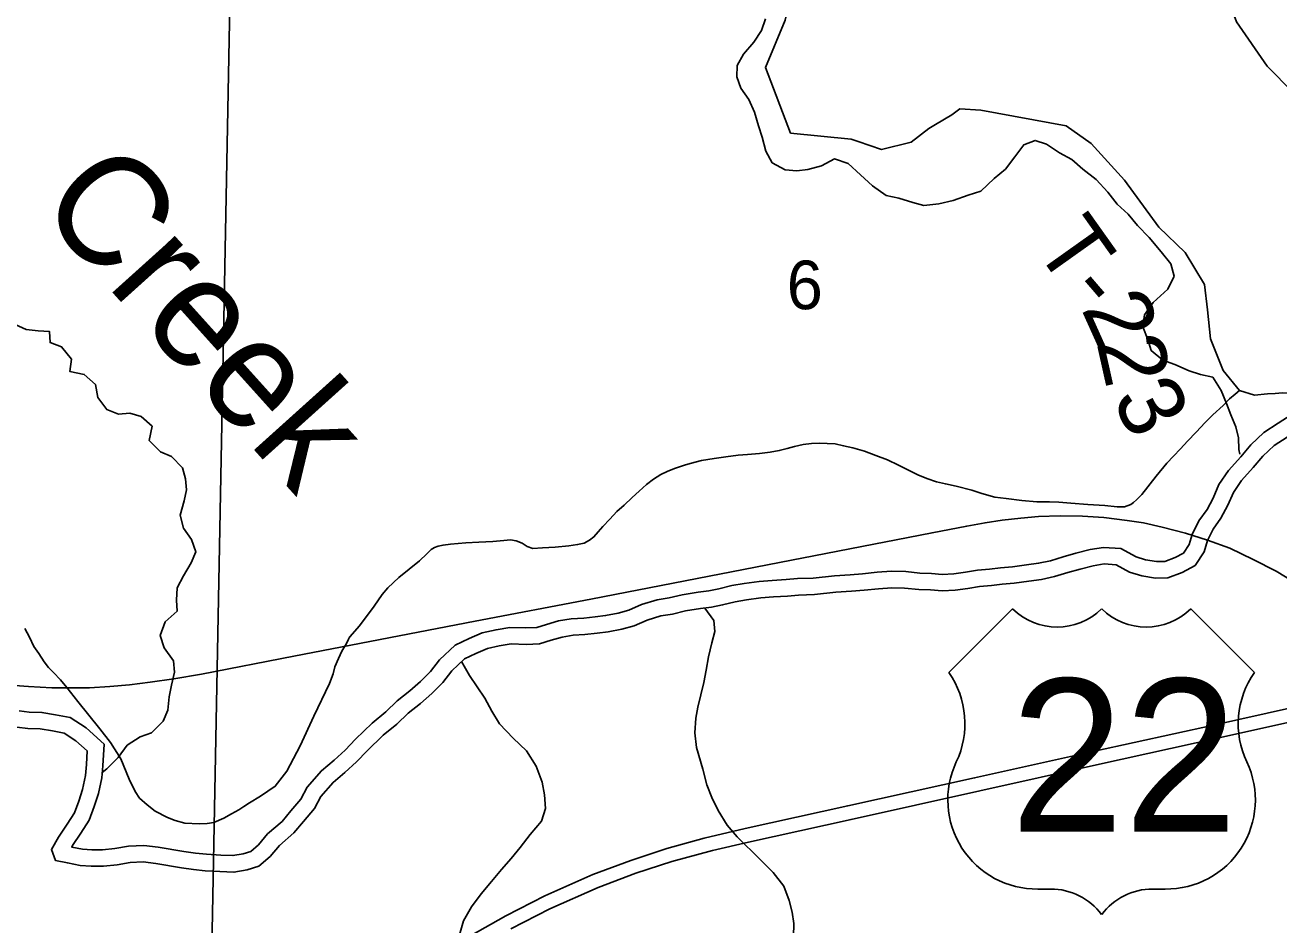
# Model space of a CAD drawing. Extents: x -19 to 40.8, y -1.8 to 26.1.
# Drawn here: x 3.175 to 4.257, y 14.667 to 15.443 of the extents above; entities that cross this region are included whole.
import ezdxf

# ---------------------------------------------------------------- set-up
doc = ezdxf.new("R2010")
doc.units = 0
for name, color, linetype in [('GM_X_Interchange_Ramps', 7, 'Continuous'), ('GM_X_Minor_River', 7, 'Continuous'), ('GM_X_Section', 7, 'Continuous'), ('GM_X_Section_Text', 7, 'Continuous'), ('GM_X_State_Route', 7, 'Continuous'), ('GM_X_State_Shield', 7, 'Continuous'), ('GM_X_Township_Road', 7, 'Continuous'), ('GM_X_Township_Road_Text', 7, 'Continuous'), ('GM_X_Unincorporated_Location', 7, 'Continuous'), ('RW_P_Text', 7, 'Continuous')]:
    doc.layers.add(name, color=color, linetype=linetype)

msp = doc.modelspace()

# ---------------------------------------------------------------- linework, layer by layer
at = {"layer": 'GM_X_Interchange_Ramps'}
msp.add_lwpolyline([(4.2703, 14.9621), (4.2543, 14.9719), (4.2343, 14.9821), (4.2142, 14.9918), (4.1949, 14.9988), (4.176, 15.0048), (4.156, 15.0099), (4.1397, 15.0135), (4.1257, 15.0157), (4.1054, 15.0183), (4.0871, 15.0194), (4.0678, 15.0197), (4.0492, 15.019), (4.034, 15.0177), (4.0177, 15.016), (4.003, 15.0137), (3.9873, 15.0109), (3.9573, 15.0051), (3.663, 14.9479), (3.5632, 14.9288), (3.4066, 14.8986), (3.327, 14.8831), (3.303, 14.8791), (3.2825, 14.8761), (3.2649, 14.8739), (3.2478, 14.8723), (3.2303, 14.8714), (3.2144, 14.8713), (3.1979, 14.8714), (3.1777, 14.8723), (3.1582, 14.8739)], dxfattribs=at)
at = {"layer": 'GM_X_Section'}
for points in [[(3.8136, 15.4486), (3.8102, 15.4383), (3.8035, 15.4283), (3.7945, 15.418), (3.7892, 15.4081), (3.7889, 15.3986), (3.7924, 15.3887), (3.7993, 15.3789), (3.804, 15.3679), (3.8075, 15.3562), (3.8106, 15.3463), (3.8138, 15.3342), (3.8192, 15.3243), (3.8306, 15.3183), (3.8405, 15.3173), (3.85, 15.3185), (3.8618, 15.3216), (3.8731, 15.3278), (3.8849, 15.3237), (3.8956, 15.3139), (3.906, 15.3045), (3.9178, 15.2962), (3.9285, 15.2937), (3.9407, 15.29), (3.9502, 15.2874), (3.9631, 15.289), (3.9756, 15.2918), (3.9885, 15.2964), (3.9995, 15.2999), (4.0108, 15.3107), (4.0206, 15.3187), (4.0288, 15.3294), (4.0364, 15.3398), (4.0462, 15.3436), (4.0561, 15.3403), (4.0672, 15.3328), (4.0779, 15.3272), (4.0874, 15.3189), (4.0989, 15.3099), (4.1089, 15.2989), (4.117, 15.2887), (4.1265, 15.2801), (4.1346, 15.2702), (4.1446, 15.2597), (4.1549, 15.2476), (4.1634, 15.237), (4.1661, 15.2264), (4.1609, 15.2153), (4.1481, 15.2038), (4.1406, 15.1931), (4.1391, 15.1829), (4.1434, 15.1719), (4.1465, 15.1624), (4.1565, 15.1541), (4.1668, 15.1504), (4.1793, 15.1448), (4.1889, 15.1415), (4.1995, 15.1393), (4.2068, 15.1279), (4.2115, 15.1166), (4.215, 15.1067), (4.2193, 15.0965), (4.2216, 15.087), (4.2221, 15.0768), (4.2229, 15.073)], [(3.1662, 15.1849), (3.1757, 15.1805), (3.186, 15.1794), (3.1959, 15.1787), (3.1963, 15.1692), (3.2062, 15.1655), (3.2147, 15.1549), (3.2133, 15.1443), (3.2258, 15.1417), (3.2354, 15.1331), (3.2374, 15.1217), (3.2451, 15.1115), (3.2554, 15.1074), (3.2652, 15.1082), (3.2748, 15.1053), (3.2843, 15.097), (3.2818, 15.0848), (3.2914, 15.075), (3.3009, 15.0709), (3.3105, 15.0611), (3.3132, 15.0516), (3.314, 15.0421), (3.3119, 15.0326), (3.3085, 15.0204), (3.3113, 15.009), (3.3182, 14.9992), (3.3221, 14.9886), (3.318, 14.9791), (3.3113, 14.968), (3.306, 14.9577), (3.3054, 14.947), (3.3058, 14.9375), (3.2956, 14.9283), (3.2912, 14.9165), (3.2947, 14.9059)], [(4.2713, 15.1093), (4.2561, 15.0997), (4.2437, 15.0917), (4.2323, 15.081), (4.2237, 15.0706), (4.213, 15.0589), (4.2049, 15.0466), (4.1999, 15.035), (4.1946, 15.0252), (4.1876, 15.0154), (4.1818, 15.0035), (4.1791, 14.9949), (4.1743, 14.9876), (4.1672, 14.9836), (4.1581, 14.9802), (4.1511, 14.9802), (4.1415, 14.9817), (4.1333, 14.9842), (4.1203, 14.9914), (4.1052, 14.9924), (4.0936, 14.9905), (4.0814, 14.9875), (4.0704, 14.9843), (4.0595, 14.9809), (4.0492, 14.9788), (4.0388, 14.9773), (4.0267, 14.9757), (4.0165, 14.9749), (4.007, 14.9736), (3.9965, 14.9728), (3.9862, 14.9711), (3.976, 14.9696), (3.9661, 14.9692), (3.9568, 14.9699), (3.9468, 14.9702), (3.9346, 14.9716), (3.9223, 14.9719), (3.91, 14.971), (3.8973, 14.9697)], [(3.8987, 14.9556), (3.9112, 14.9568), (3.9226, 14.9577), (3.9336, 14.9574), (3.9458, 14.956), (3.9561, 14.9557), (3.9659, 14.955), (3.9773, 14.9555), (3.9883, 14.9571), (3.9982, 14.9587), (4.0085, 14.9595), (4.0179, 14.9607), (4.0282, 14.9616), (4.0407, 14.9632), (4.0517, 14.9648), (4.0631, 14.9672), (4.0745, 14.9707), (4.0851, 14.9738), (4.0964, 14.9766), (4.1059, 14.9782), (4.1162, 14.9775), (4.1276, 14.9711), (4.1383, 14.9678), (4.1501, 14.966), (4.1607, 14.9661), (4.1732, 14.9707), (4.1842, 14.9769), (4.1921, 14.9887), (4.195, 14.9983), (4.1999, 15.0082), (4.2066, 15.0177), (4.2126, 15.0288), (4.2175, 15.0399), (4.2242, 15.0502), (4.2344, 15.0613), (4.2427, 15.0712), (4.2525, 15.0804), (4.2638, 15.0877)], [(3.8973, 14.9697), (3.8867, 14.9689), (3.8732, 14.968), (3.8548, 14.966), (3.8412, 14.9655), (3.8315, 14.9647), (3.8194, 14.9638), (3.808, 14.9629), (3.7953, 14.9612), (3.7846, 14.9595), (3.7733, 14.9567), (3.7646, 14.9549), (3.7555, 14.9537), (3.7418, 14.9516), (3.7304, 14.9488), (3.7202, 14.9472), (3.7067, 14.9431), (3.6956, 14.9382), (3.6865, 14.9358), (3.6756, 14.9336), (3.6667, 14.9325), (3.6567, 14.9313), (3.646, 14.9309), (3.6349, 14.929), (3.6245, 14.926), (3.6162, 14.9234), (3.6068, 14.923), (3.5931, 14.9233), (3.5811, 14.9214), (3.5691, 14.9187), (3.5579, 14.9138), (3.5458, 14.9081), (3.5324, 14.8955), (3.5244, 14.8853), (3.5159, 14.8767), (3.5068, 14.8688), (3.4958, 14.8601), (3.486, 14.8505), (3.4743, 14.8409), (3.4597, 14.8269), (3.4509, 14.8175), (3.4413, 14.8088), (3.4304, 14.7998), (3.4181, 14.7855), (3.4125, 14.7752), (3.404, 14.7651), (3.3964, 14.756), (3.384, 14.7453), (3.3761, 14.7357), (3.3695, 14.73), (3.3629, 14.728), (3.354, 14.7265), (3.3435, 14.727), (3.3313, 14.7277), (3.3216, 14.7287), (3.3118, 14.7301), (3.2896, 14.7337), (3.2771, 14.7353), (3.264, 14.7348), (3.2522, 14.7327), (3.2416, 14.7316), (3.2322, 14.7315), (3.2241, 14.7321), (3.2149, 14.7339), (3.2155, 14.7351), (3.2228, 14.7458), (3.23, 14.7571), (3.2344, 14.7688), (3.2381, 14.78), (3.241, 14.7935), (3.2417, 14.8041), (3.2428, 14.8228), (3.2274, 14.8368), (3.2137, 14.8457), (3.2009, 14.8481), (3.1892, 14.8501), (3.1781, 14.8504), (3.1695, 14.8513)], [(3.1676, 14.8372), (3.1771, 14.8362), (3.1878, 14.8359), (3.1984, 14.8341), (3.2083, 14.8323), (3.2186, 14.8255), (3.2282, 14.8168), (3.2276, 14.805), (3.2269, 14.7955), (3.2243, 14.7837), (3.221, 14.7735), (3.2173, 14.7635), (3.2109, 14.7536), (3.2034, 14.7425), (3.1974, 14.7318), (3.2009, 14.7224), (3.2112, 14.7202), (3.2222, 14.718), (3.2317, 14.7173), (3.2424, 14.7174), (3.2541, 14.7186), (3.2655, 14.7206), (3.2765, 14.7211), (3.2876, 14.7196), (3.3096, 14.716), (3.3199, 14.7146), (3.3302, 14.7135), (3.3427, 14.7129), (3.3549, 14.7122), (3.3662, 14.7142), (3.3765, 14.7173), (3.3863, 14.7258), (3.3942, 14.7353), (3.4066, 14.7461), (3.4149, 14.756), (3.4243, 14.7671), (3.4299, 14.7774), (3.4404, 14.7897), (3.4506, 14.7981), (3.4608, 14.8073), (3.4698, 14.8169), (3.4838, 14.8303), (3.4955, 14.8399), (3.5053, 14.8495), (3.5158, 14.8579), (3.5256, 14.8663), (3.5351, 14.8759), (3.5429, 14.8859), (3.5539, 14.8962), (3.5637, 14.9008), (3.5736, 14.9051), (3.5838, 14.9075), (3.594, 14.9091), (3.607, 14.9088), (3.6187, 14.9093), (3.6286, 14.9124), (3.6381, 14.9151), (3.6475, 14.9167), (3.6578, 14.9172), (3.6684, 14.9184), (3.6779, 14.9196), (3.6897, 14.922), (3.7003, 14.9247), (3.7116, 14.9298), (3.7234, 14.9333), (3.7332, 14.9349), (3.7446, 14.9376), (3.7575, 14.9396), (3.767, 14.9409), (3.7765, 14.9428), (3.7875, 14.9456), (3.7973, 14.9472), (3.8095, 14.9488), (3.8205, 14.9497), (3.8326, 14.9505), (3.8421, 14.9513), (3.8558, 14.9518), (3.8744, 14.9539), (3.8877, 14.9548), (3.8987, 14.9556)], [(3.7612, 14.9401), (3.769, 14.9295), (3.7698, 14.92), (3.7673, 14.9101), (3.7643, 14.8979), (3.7625, 14.8865), (3.7603, 14.8758), (3.7552, 14.8545), (3.7534, 14.845), (3.7527, 14.8324), (3.754, 14.8199), (3.7595, 14.801), (3.763, 14.7877), (3.7673, 14.7767), (3.7727, 14.7653), (3.7804, 14.7529), (3.7892, 14.7427), (3.8091, 14.7231), (3.8202, 14.7118), (3.8295, 14.7001), (3.8341, 14.6879), (3.8365, 14.6777), (3.8381, 14.6678), (3.8378, 14.6568)], [(3.2947, 14.9059), (3.3028, 14.8946), (3.3036, 14.8847), (3.3011, 14.8737), (3.2989, 14.8634), (3.2978, 14.852), (3.2937, 14.8424), (3.2839, 14.8325), (3.2741, 14.829), (3.2627, 14.8217), (3.2549, 14.8113), (3.2451, 14.8014), (3.2413, 14.7983)], [(3.5514, 14.8939), (3.5582, 14.8818), (3.5713, 14.8625), (3.5774, 14.8512), (3.584, 14.8402), (3.5959, 14.8278), (3.6074, 14.8168), (3.6158, 14.8036), (3.6209, 14.79), (3.6229, 14.779), (3.6237, 14.7672), (3.6204, 14.7561), (3.6106, 14.7447), (3.602, 14.7336), (3.5941, 14.724), (3.5858, 14.7144), (3.5772, 14.7041), (3.5681, 14.6934), (3.5599, 14.6823), (3.5531, 14.6701), (3.5495, 14.6583)]]:
    msp.add_lwpolyline(points, dxfattribs=at)
at = {"layer": 'GM_X_State_Route'}
for points in [[(4.3257, 15.3498), (4.3251, 15.3505), (4.2689, 15.3849), (4.2466, 15.4076), (4.2199, 15.4459), (4.2025, 15.4933), (4.1605, 15.58), (4.1444, 15.6081), (4.1337, 15.6283), (4.1173, 15.6538), (4.0927, 15.6836), (4.0704, 15.7184), (4.0341, 15.8035), (4.0106, 15.82), (3.993, 15.8334), (3.9881, 15.843), (3.9886, 15.8546), (3.9895, 15.8715), (3.9882, 15.8783)], [(3.8936, 15.3428), (3.8875, 15.3448), (3.8353, 15.35), (3.8135, 15.4066), (3.8306, 15.4474), (3.843, 15.5014), (3.8436, 15.5139)], [(4.2225, 15.1277), (4.2084, 15.1452), (4.1975, 15.1723), (4.195, 15.1975), (4.1924, 15.2192), (4.1758, 15.2468), (4.1531, 15.2688), (4.1233, 15.3094), (4.0946, 15.341), (4.0729, 15.3561), (3.9994, 15.3697), (3.9814, 15.3708), (3.9745, 15.3656), (3.9603, 15.3572)], [(3.9603, 15.3572), (3.9546, 15.3539), (3.9392, 15.3421), (3.9138, 15.3358), (3.8936, 15.3428)], [(4.2225, 15.1277), (4.2189, 15.1246), (4.214, 15.1207), (4.2085, 15.115), (4.1997, 15.1068), (4.1929, 15.1002), (4.1852, 15.0919), (4.1778, 15.084), (4.1716, 15.0774), (4.1657, 15.0712), (4.16, 15.065), (4.1507, 15.054), (4.1382, 15.038), (4.1336, 15.0336), (4.1312, 15.0312), (4.1287, 15.0294), (4.1233, 15.0275), (4.1169, 15.0275), (4.1065, 15.0285), (4.0918, 15.0296), (4.0771, 15.0307), (4.0668, 15.0316), (4.0586, 15.0318), (4.0476, 15.0318), (4.0349, 15.033), (4.0212, 15.0345), (4.0114, 15.0358), (4.0003, 15.0389), (3.9915, 15.0417), (3.9781, 15.0453), (3.9689, 15.0472), (3.9612, 15.049), (3.9527, 15.0518), (3.945, 15.0551), (3.9375, 15.0587), (3.9283, 15.0635), (3.9188, 15.0679), (3.9087, 15.0717), (3.899, 15.0754), (3.8889, 15.0784), (3.881, 15.0802), (3.8737, 15.0818), (3.8667, 15.082), (3.8603, 15.0824), (3.8533, 15.082), (3.846, 15.0811), (3.8386, 15.0796), (3.8322, 15.0778), (3.8254, 15.076), (3.8176, 15.0745), (3.8084, 15.0736), (3.7981, 15.0725), (3.7899, 15.0719), (3.7794, 15.0705), (3.7693, 15.0692), (3.7583, 15.0673), (3.7486, 15.0648), (3.7438, 15.0633), (3.7352, 15.0606), (3.7286, 15.058), (3.7233, 15.0554), (3.717, 15.0512), (3.711, 15.0466), (3.7046, 15.0409), (3.6985, 15.0354), (3.6915, 15.029), (3.6853, 15.0235), (3.6792, 15.0169), (3.6732, 15.0105), (3.6693, 15.0059), (3.6655, 15.0015), (3.6618, 14.9986), (3.6572, 14.9962), (3.6514, 14.9949), (3.644, 14.9938), (3.6321, 14.9927), (3.6213, 14.992), (3.6128, 14.9916), (3.6079, 14.9932), (3.6037, 14.996), (3.5983, 14.998), (3.5935, 14.9989), (3.5877, 14.9984), (3.5784, 14.9976), (3.5662, 14.9969), (3.5551, 14.9965), (3.5418, 14.9953), (3.5354, 14.9945), (3.531, 14.9934), (3.5279, 14.9923), (3.525, 14.9905), (3.5215, 14.9868), (3.5151, 14.9809), (3.4971, 14.9665), (3.4877, 14.9577), (3.4827, 14.9518), (3.476, 14.9417), (3.4632, 14.9247), (3.455, 14.9154), (3.4544, 14.9144)], [(4.343, 15.1054), (4.3357, 15.1139), (4.3291, 15.1194), (4.3195, 15.127), (4.316, 15.129), (4.3128, 15.1303), (4.309, 15.1312), (4.3046, 15.1308), (4.2964, 15.1287), (4.2914, 15.1264), (4.2863, 15.1246), (4.2796, 15.1242), (4.2697, 15.1251), (4.2596, 15.1257), (4.2534, 15.1253), (4.2468, 15.1249), (4.2355, 15.1239), (4.2225, 15.1277)], [(3.4544, 14.9144), (3.4539, 14.9134), (3.452, 14.9096), (3.4479, 14.903), (3.445, 14.8967), (3.4421, 14.8894), (3.4406, 14.8834), (3.4374, 14.8749), (3.4238, 14.8469), (3.4122, 14.8213), (3.4005, 14.7994), (3.3905, 14.7864), (3.3779, 14.7777), (3.3683, 14.772), (3.3634, 14.7689), (3.359, 14.7661), (3.3527, 14.7625), (3.3463, 14.7588), (3.3375, 14.755), (3.3318, 14.7542), (3.325, 14.7539), (3.3126, 14.7545), (3.3041, 14.7567), (3.2975, 14.7595), (3.287, 14.7649), (3.2799, 14.7704), (3.2735, 14.7761), (3.2696, 14.7819), (3.2645, 14.7926), (3.2572, 14.8101), (3.2484, 14.8241), (3.2393, 14.836), (3.2201, 14.8595), (3.2107, 14.8716), (3.2052, 14.8782), (3.1992, 14.8845), (3.195, 14.8887), (3.1913, 14.8936), (3.1865, 14.9008), (3.1823, 14.907), (3.1785, 14.9149), (3.1744, 14.9224)]]:
    msp.add_lwpolyline(points, dxfattribs=at)
at = {"layer": 'GM_X_State_Shield'}
for p, q in [((4.0267, 14.9394), (3.9718, 14.8845)), ((4.2354, 14.8845), (4.1805, 14.9394)), ((4.0487, 14.6977), (4.0597, 14.6977)), ((4.1476, 14.6977), (4.1585, 14.6977))]:
    msp.add_line(p, q, dxfattribs=at)
for centre, radius, start, end in [((4.0652, 14.9786), 0.0549, 225.573, 314.427), ((4.1421, 14.9786), 0.0549, 225.573, 314.427), ((3.9088, 14.8404), 0.0769, 334.5471, 35.0009), ((4.2984, 14.8404), 0.0769, 144.9991, 205.4529), ((4.0478, 14.7746), 0.0769, 154.8319, 270.6383), ((4.1594, 14.7746), 0.0769, 269.3617, 25.1681), ((4.0597, 14.6428), 0.0549, 36.8699, 90), ((4.1476, 14.6428), 0.0549, 90, 143.1301)]:
    msp.add_arc(centre, radius, start, end, dxfattribs=at)
at = {"layer": 'GM_X_Township_Road'}
for points in [[(3.5585, 14.6569), (3.5894, 14.6745), (3.6232, 14.6919), (3.6647, 14.7102), (3.6973, 14.7224), (3.7285, 14.7327), (3.7608, 14.7417), (3.7961, 14.7499), (3.8846, 14.7696), (3.994, 14.7936), (4.0975, 14.8166), (4.2003, 14.8392), (4.2682, 14.8544)], [(3.5938, 14.6633), (3.6276, 14.6807), (3.6691, 14.699), (3.7016, 14.7113), (3.7329, 14.7215), (3.7678, 14.7308), (3.7989, 14.738), (3.8874, 14.7577), (3.9984, 14.7824), (4.1019, 14.8054), (4.2047, 14.828), (4.271, 14.8427)]]:
    msp.add_lwpolyline(points, dxfattribs=at)
at = {"layer": 'RW_P_Text'}
for points in [[(2.3634, 15.8992), (3.3595, 15.883), (3.3355, 14.6314), (2.3446, 14.653)], [(3.3595, 15.883), (4.3635, 15.8676), (4.3391, 14.8802), (4.3324, 14.6079), (3.3355, 14.6314)]]:
    msp.add_lwpolyline(points, close=True, dxfattribs=at)

# ---------------------------------------------------------------- texts
at = {"layer": 'GM_X_Minor_River'}
msp.add_text('Creek', height=0.09469, rotation=311.9835, dxfattribs=at).set_placement((3.183, 15.2869))
at = {"layer": 'GM_X_Section_Text'}
msp.add_text('6', height=0.0419, rotation=0, dxfattribs=at).set_placement((3.8319, 15.198))
at = {"layer": 'GM_X_State_Shield'}
msp.add_text('22', height=0.13184, dxfattribs=at).set_placement((4.0248, 14.7472))
at = {"layer": 'GM_X_Township_Road_Text'}
for s, rotation, p in [('T', 305.3972, (4.0446, 15.2516)), ('-', 310.6841, (4.0728, 15.2125)), ('2', 294.251, (4.0857, 15.1984)), ('2', 282.649, (4.0991, 15.1694)), ('3', 297.0976, (4.112, 15.1206))]:
    msp.add_text(s, height=0.0568, rotation=rotation, dxfattribs=at).set_placement(p)
at = {"layer": 'GM_X_Unincorporated_Location'}
for s, p in [('0', (4.1035, 14.812)), ('/', (4.1036, 14.812))]:
    msp.add_text(s, height=0.000189, dxfattribs=at).set_placement(p)
msp.add_text('22', height=0.000189, rotation=0, dxfattribs=at).set_placement((4.0644, 14.7728))

doc.saveas('drawing.dxf')
